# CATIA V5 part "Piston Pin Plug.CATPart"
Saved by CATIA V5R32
Part number: Piston Pin Plug
Bounding box of the stored display mesh (mm): x -11 to 11, y -10.833 to 10.833, z -15 to 0
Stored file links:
  D:\PROJECTS\Project 2022\CATIA V5 6R 2022\Resources\Part Files\c13_catia_v5_6r2022_prt\c13_catia_v5-6r2022_figr_13-41\Part & Asm files\Piston Pin Plug.CATPart
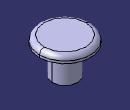
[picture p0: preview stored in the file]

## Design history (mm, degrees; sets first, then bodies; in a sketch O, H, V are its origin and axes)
Body1 (main body)
  Sketch1 on xy-plane, origin (0, 0, 0), H (1, 0, 0), V (0, 1, 0)
    circle A1 centre (0, 0) radius 11
    circle A2 centre (0, 0) radius 5.5
    radius A2 = 5.5
    radius A1 = 11
  MultiPad1: profile Sketch1, domains (length 15; length 3)
  Fillet1: radius 2, on 1 edge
